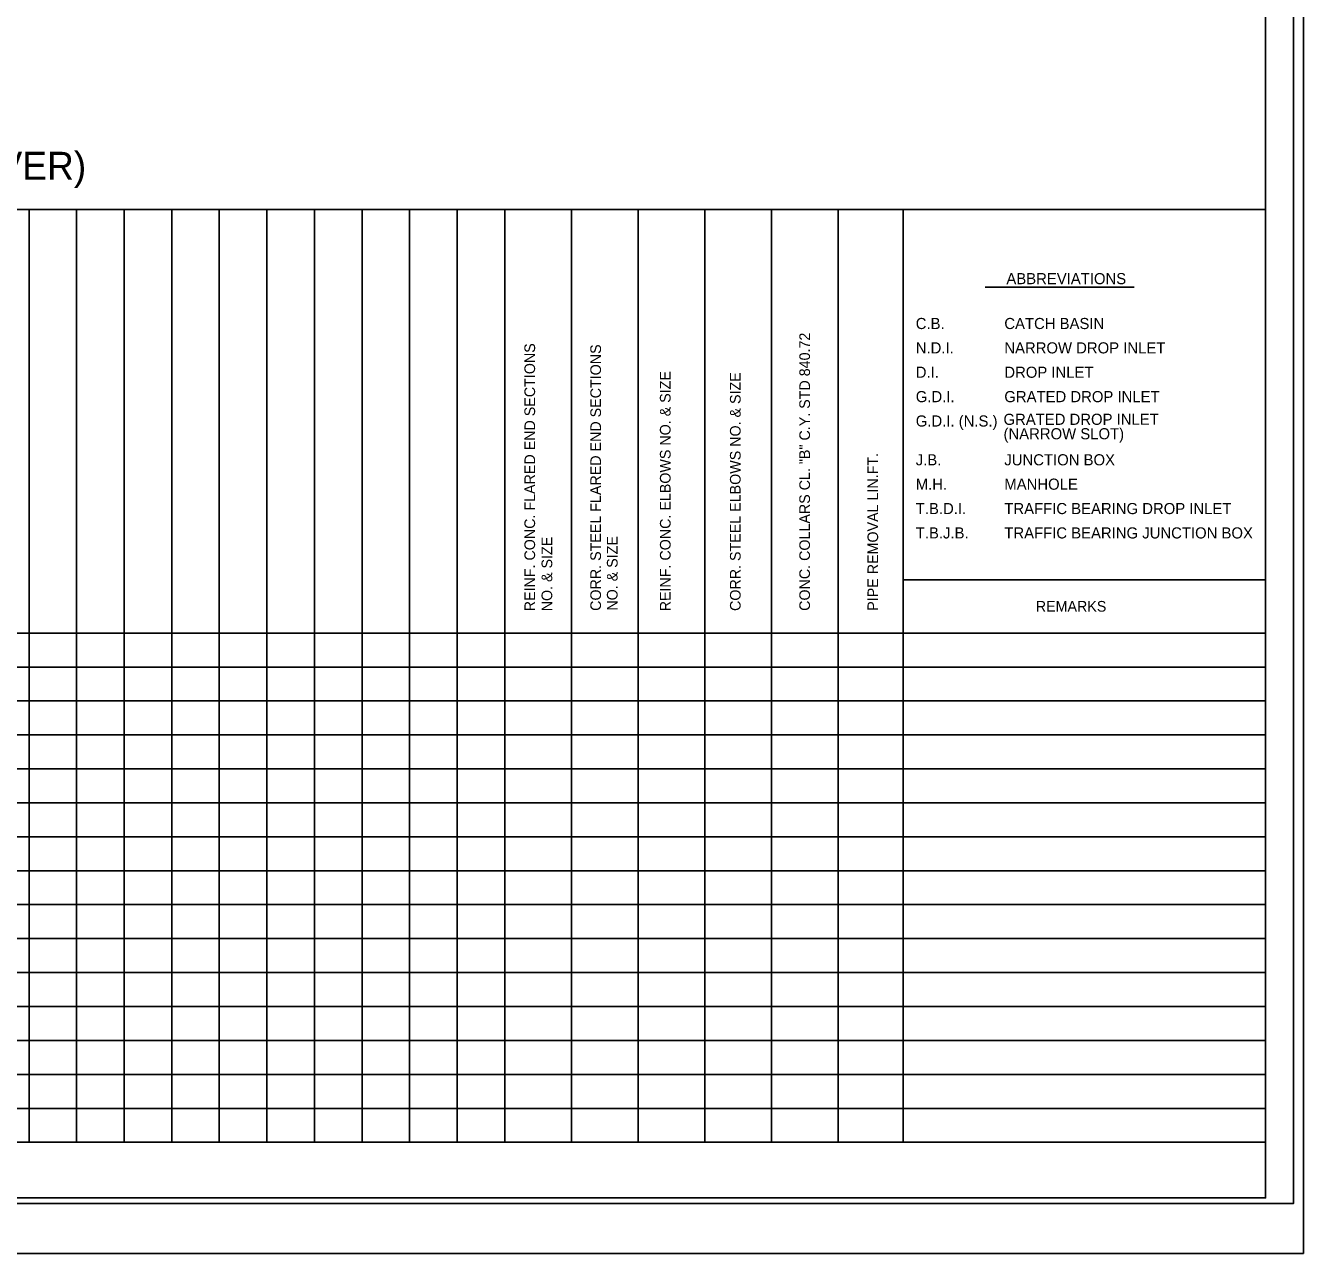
# Model space of a CAD drawing. Extents: x 2530399 to 2530799, y 189629 to 189994.
# Drawn here: x 2530741.2 to 2530798.7, y 189849.1 to 189904.4 of the extents above; entities that cross this region are included whole.
import ezdxf

# ---------------------------------------------------------------- set-up
doc = ezdxf.new("R2010")
doc.units = 0
for name, color, linetype in [('Sheet Plan CELL', 7, 'Continuous'), ('Typical Asphalt at Bridge Approach CELL', 7, 'Continuous'), ('Typical Detail Pavement Repair CELL', 7, 'Continuous'), ('Typical Detail Wedge1 CELL', 7, 'Continuous'), ('Typical Pavement Slope Information CELL', 7, 'Continuous'), ('Typical Shoulder Slope CELL', 7, 'Continuous')]:
    doc.layers.add(name, color=color, linetype=linetype)

msp = doc.modelspace()

# ---------------------------------------------------------------- linework, layer by layer
at = {"layer": 'Sheet Plan CELL'}
msp.add_line((2530630.272, 189849.139), (2530798.672, 189849.139), dxfattribs=at)
at = {"layer": 'Typical Detail Pavement Repair CELL'}
msp.add_lwpolyline([(2530798.222, 189956.894), (2530631.572, 189956.894), (2530631.572, 189851.384), (2530798.222, 189851.384)], close=True, dxfattribs=at)
at = {"layer": 'Typical Detail Wedge1 CELL'}
msp.add_lwpolyline([(2530798.672, 189959.139), (2530630.272, 189959.139), (2530630.272, 189849.139), (2530798.672, 189849.139)], close=True, dxfattribs=at)
at = {"layer": 'Typical Pavement Slope Information CELL'}
msp.add_line((2530791.055, 189892.591), (2530784.355, 189892.591), dxfattribs=at)
msp.add_lwpolyline([(2530796.972, 189956.639), (2530646.972, 189956.639), (2530646.972, 189851.639), (2530796.972, 189851.639)], close=True, dxfattribs=at)
at = {"layer": 'Typical Shoulder Slope CELL'}
for p, q in [((2530796.962, 189896.089), (2530646.962, 189896.074)), ((2530741.346, 189854.139), (2530741.346, 189896.074)), ((2530743.486, 189854.139), (2530743.486, 189896.074)), ((2530745.626, 189854.139), (2530745.626, 189896.074)), ((2530747.766, 189854.139), (2530747.766, 189896.074)), ((2530749.906, 189854.139), (2530749.906, 189896.074)), ((2530752.046, 189854.139), (2530752.046, 189896.074)), ((2530754.186, 189854.139), (2530754.186, 189896.074)), ((2530756.326, 189854.139), (2530756.326, 189896.074)), ((2530758.466, 189854.139), (2530758.466, 189896.074)), ((2530760.606, 189854.139), (2530760.606, 189896.074)), ((2530762.746, 189854.139), (2530762.746, 189896.074)), ((2530765.746, 189854.139), (2530765.746, 189896.074)), ((2530768.746, 189854.139), (2530768.746, 189896.074)), ((2530771.746, 189854.139), (2530771.746, 189896.074)), ((2530774.746, 189854.139), (2530774.746, 189896.074)), ((2530777.746, 189854.139), (2530777.746, 189896.074)), ((2530780.673, 189854.139), (2530780.671, 189896.089)), ((2530796.962, 189879.434), (2530780.672, 189879.434)), ((2530796.962, 189877.039), (2530646.962, 189877.039)), ((2530796.962, 189875.514), (2530646.962, 189875.514)), ((2530796.962, 189873.989), (2530646.962, 189873.989)), ((2530796.962, 189872.464), (2530646.962, 189872.464)), ((2530796.962, 189870.934), (2530646.962, 189870.934)), ((2530796.962, 189869.409), (2530646.962, 189869.409)), ((2530796.962, 189867.879), (2530646.962, 189867.879)), ((2530796.962, 189866.354), (2530646.962, 189866.354)), ((2530796.962, 189864.829), (2530646.962, 189864.829)), ((2530796.962, 189863.299), (2530646.967, 189863.299)), ((2530796.962, 189861.774), (2530646.967, 189861.774)), ((2530796.962, 189860.244), (2530646.967, 189860.244)), ((2530796.962, 189858.719), (2530646.967, 189858.719)), ((2530796.962, 189857.194), (2530646.967, 189857.194)), ((2530796.962, 189855.664), (2530646.967, 189855.664)), ((2530796.962, 189854.139), (2530646.967, 189854.139))]:
    msp.add_line(p, q, dxfattribs=at)

# ---------------------------------------------------------------- texts
at = {"layer": 'Typical Asphalt at Bridge Approach CELL'}
for s, height, p in [('C.B.', 0.5, (2530781.233, 189890.713)), ('CATCH BASIN', 0.50001, (2530785.217, 189890.713)), ('N.D.I.', 0.5, (2530781.233, 189889.617)), ('NARROW DROP INLET', 0.50001, (2530785.217, 189889.617)), ('D.I.', 0.5, (2530781.233, 189888.521)), ('DROP INLET', 0.5, (2530785.217, 189888.521)), ('G.D.I.', 0.5, (2530781.233, 189887.424)), ('GRATED DROP INLET', 0.50001, (2530785.217, 189887.424)), ('G.D.I. (N.S.)', 0.50001, (2530781.233, 189886.328)), ('J.B.', 0.5, (2530781.233, 189884.583)), ('JUNCTION BOX', 0.50001, (2530785.217, 189884.583)), ('M.H.', 0.5, (2530781.233, 189883.487)), ('MANHOLE', 0.5, (2530785.217, 189883.487)), ('T.B.D.I.', 0.5, (2530781.233, 189882.39)), ('TRAFFIC BEARING DROP INLET', 0.50001, (2530785.217, 189882.39)), ('T.B.J.B.', 0.5, (2530781.233, 189881.294)), ('TRAFFIC BEARING JUNCTION BOX', 0.50001, (2530785.217, 189881.294))]:
    msp.add_text(s, height=height, dxfattribs=at).set_placement(p)
for s, p in [('GRATED DROP INLET', (2530785.18, 189886.403)), ('(NARROW SLOT)', (2530785.181, 189885.753))]:
    msp.add_text(s, height=0.50001, rotation=0.02739, dxfattribs=at).set_placement(p)
at = {"layer": 'Typical Pavement Slope Information CELL'}
for s, height, p in [('LIST OF PIPES, ENDWALLS, ETC. (FOR PIPES 54" & OVER)', 1.25001, (2530697.162, 189897.434)), ('ABBREVIATIONS', 0.50001, (2530785.31, 189892.731)), ('REMARKS', 0.48, (2530786.632, 189878.004))]:
    msp.add_text(s, height=height, dxfattribs=at).set_placement(p)
for s, height, rotation, p in [('CONC. COLLARS CL. "B" C.Y. STD 840.72', 0.48, 90, (2530776.476, 189878.039)), ('REINF. CONC. FLARED END SECTIONS', 0.48, 90, (2530764.111, 189878.019)), ('CORR. STEEL FLARED END SECTIONS', 0.48, 90, (2530767.075, 189878.039)), ('REINF. CONC. ELBOWS NO. & SIZE', 0.47983, 90.02578, (2530770.208, 189878.019)), ('CORR. STEEL ELBOWS NO. & SIZE', 0.48, 90, (2530773.356, 189878.034)), ('PIPE REMOVAL LIN.FT.', 0.48, 90, (2530779.542, 189878.044)), ('NO. & SIZE', 0.48, 90, (2530764.881, 189878.019)), ('NO. & SIZE', 0.48, 90, (2530767.821, 189878.049))]:
    msp.add_text(s, height=height, rotation=rotation, dxfattribs=at).set_placement(p)

doc.saveas('drawing.dxf')
